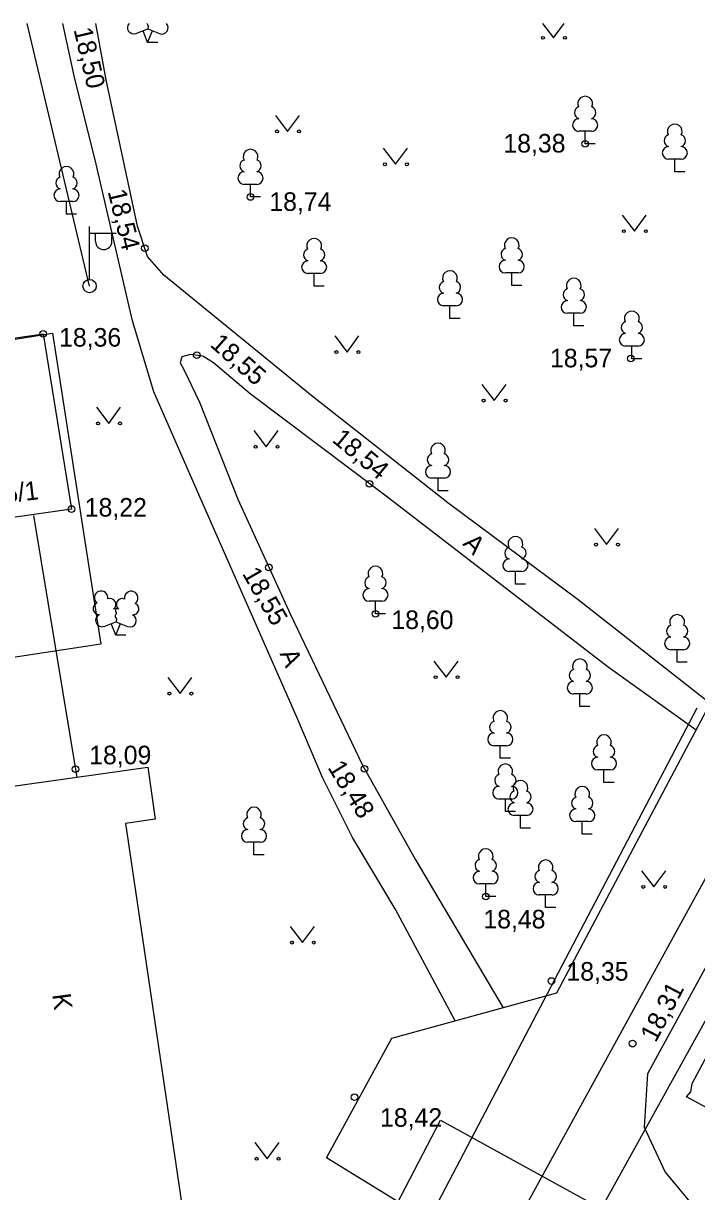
# Model space of a CAD drawing. Extents: x 713540 to 713867, y 6589774 to 6590061.
# Drawn here: x 713723 to 713748.39, y 6590016.58 to 6590060.64 of the extents above; entities that cross this region are included whole.
import ezdxf

# ---------------------------------------------------------------- set-up
doc = ezdxf.new("R2010")
doc.units = 0
for name, color, linetype in [('HALJASTUS', 7, 'Continuous'), ('HOONE', 7, 'Continuous'), ('HOONEDET', 7, 'Continuous'), ('KORGUS', 7, 'Continuous'), ('MPKAABEL', 7, 'Continuous'), ('POST', 7, 'Continuous'), ('PUU', 7, 'Continuous'), ('TEE', 7, 'Continuous'), ('TTRASS', 7, 'Continuous'), ('Слой 1', 7, 'Continuous')]:
    doc.layers.add(name, color=color, linetype=linetype)

msp = doc.modelspace()

# ---------------------------------------------------------------- linework, layer by layer
at = {"layer": 'HALJASTUS'}
for p, q in [((713742.583, 6590060.636), (713743, 6590060.09)), ((713743, 6590060.09), (713743.401, 6590060.636)), ((713732.507, 6590057.167), (713732.97, 6590056.56)), ((713732.97, 6590056.56), (713733.416, 6590057.167)), ((713736.577, 6590055.927), (713737.04, 6590055.32)), ((713737.04, 6590055.32), (713737.486, 6590055.927)), ((713745.587, 6590053.407), (713746.05, 6590052.8)), ((713746.05, 6590052.8), (713746.496, 6590053.407)), ((713734.747, 6590048.847), (713735.21, 6590048.24)), ((713735.21, 6590048.24), (713735.656, 6590048.847)), ((713740.297, 6590047.017), (713740.76, 6590046.41)), ((713740.76, 6590046.41), (713741.206, 6590047.017)), ((713725.757, 6590046.157), (713726.22, 6590045.55)), ((713726.22, 6590045.55), (713726.666, 6590046.157)), ((713731.697, 6590045.277), (713732.16, 6590044.67)), ((713732.16, 6590044.67), (713732.606, 6590045.277)), ((713744.537, 6590041.587), (713745, 6590040.98)), ((713745, 6590040.98), (713745.446, 6590041.587)), ((713738.487, 6590036.587), (713738.95, 6590035.98)), ((713738.95, 6590035.98), (713739.396, 6590036.587)), ((713728.447, 6590035.967), (713728.91, 6590035.36)), ((713728.91, 6590035.36), (713729.356, 6590035.967)), ((713746.317, 6590028.677), (713746.78, 6590028.07)), ((713746.78, 6590028.07), (713747.226, 6590028.677)), ((713733.067, 6590026.577), (713733.53, 6590025.97)), ((713733.53, 6590025.97), (713733.976, 6590026.577)), ((713731.737, 6590018.427), (713732.2, 6590017.82)), ((713732.2, 6590017.82), (713732.646, 6590018.427))]:
    msp.add_line(p, q, dxfattribs=at)
for centre in [(713742.599, 6590060.09), (713743.428, 6590060.09), (713732.569, 6590056.56), (713733.398, 6590056.56), (713736.639, 6590055.32), (713737.468, 6590055.32), (713745.649, 6590052.8), (713746.478, 6590052.8), (713734.809, 6590048.24), (713735.638, 6590048.24), (713740.359, 6590046.41), (713741.188, 6590046.41), (713725.819, 6590045.55), (713726.648, 6590045.55), (713731.759, 6590044.67), (713732.588, 6590044.67), (713744.599, 6590040.98), (713745.428, 6590040.98), (713738.549, 6590035.98), (713739.378, 6590035.98), (713728.509, 6590035.36), (713729.338, 6590035.36), (713746.379, 6590028.07), (713747.208, 6590028.07), (713733.129, 6590025.97), (713733.958, 6590025.97), (713731.799, 6590017.82), (713732.628, 6590017.82)]:
    msp.add_circle(centre, 0.055, dxfattribs=at)
at = {"layer": 'HOONE'}
for points in [[(713711.51, 6590047.14), (713723.75, 6590048.93), (713724.82, 6590042.32), (713712.76, 6590040.59), (713711.51, 6590047.14)], [(713729.99, 6589999.65), (713748.41, 6590034.82)], [(713720.1, 6590031.52), (713727.7, 6590032.58), (713727.97, 6590030.62), (713726.86, 6590030.46), (713729.03, 6590015.74), (713722.42, 6590014.82), (713720.1, 6590031.52)]]:
    msp.add_lwpolyline(points, dxfattribs=at)
at = {"layer": 'HOONEDET'}
msp.add_lwpolyline([(713764.214, 6590011.385), (713748.01, 6590020.15), (713748.17, 6590020.34), (713748.23, 6590020.65), (713753, 6590029.57)], dxfattribs=at)
at = {"layer": 'KORGUS'}
for centre in [(713744.19, 6590056.09), (713731.57, 6590054.09), (713727.58, 6590052.16), (713723.75, 6590048.93), (713729.54, 6590048.12), (713745.91, 6590048), (713736.06, 6590043.27), (713724.82, 6590042.32), (713732.26, 6590040.12), (713736.28, 6590038.37), (713724.97, 6590032.51), (713735.87, 6590032.52), (713740.44, 6590027.71), (713742.92, 6590024.52), (713745.98, 6590022.16), (713735.49, 6590020.14)]:
    msp.add_circle(centre, 0.125, dxfattribs=at)
at = {"layer": 'MPKAABEL'}
for points in [[(713725.5, 6590050.73), (713723.14, 6590060.636)], [(713734.86, 6589982.939), (713729.11, 6589985.97), (713735.68, 6589998.99), (713741.04, 6590009.14), (713752.51, 6590029.86)]]:
    msp.add_lwpolyline(points, dxfattribs=at)
at = {"layer": 'POST'}
for p, q in [((713725.5, 6590050.98), (713725.5, 6590052.98)), ((713725.5, 6590052.73), (713726.5, 6590052.73)), ((713725.727, 6590052.409), (713725.727, 6590052.73)), ((713726.339, 6590052.409), (713726.339, 6590052.73))]:
    msp.add_line(p, q, dxfattribs=at)
msp.add_circle((713725.5, 6590050.73), 0.25, dxfattribs=at)
msp.add_arc((713726.033, 6590052.409), 0.306, 180, 0, dxfattribs=at)
at = {"layer": 'PUU'}
for p, q in [((713727.25, 6590060.255), (713727.695, 6590060.43)), ((713727.69, 6590059.92), (713727.515, 6590060.36)), ((713727.69, 6590059.92), (713727.87, 6590060.36)), ((713727.695, 6590060.43), (713728.135, 6590060.25)), ((713728.07, 6590059.92), (713727.69, 6590059.92)), ((713744.43, 6590056.565), (713743.95, 6590056.565)), ((713744.19, 6590056.09), (713744.19, 6590056.565)), ((713744.57, 6590056.09), (713744.19, 6590056.09)), ((713747.81, 6590055.515), (713747.33, 6590055.515)), ((713747.57, 6590055.04), (713747.57, 6590055.515)), ((713747.95, 6590055.04), (713747.57, 6590055.04)), ((713731.81, 6590054.565), (713731.33, 6590054.565)), ((713731.57, 6590054.09), (713731.57, 6590054.565)), ((713724.87, 6590053.915), (713724.39, 6590053.915)), ((713724.63, 6590053.44), (713724.63, 6590053.915)), ((713731.95, 6590054.09), (713731.57, 6590054.09)), ((713725.01, 6590053.44), (713724.63, 6590053.44)), ((713734.21, 6590051.205), (713733.73, 6590051.205)), ((713733.97, 6590050.73), (713733.97, 6590051.205)), ((713741.66, 6590051.225), (713741.18, 6590051.225)), ((713741.42, 6590050.75), (713741.42, 6590051.225)), ((713734.35, 6590050.73), (713733.97, 6590050.73)), ((713741.8, 6590050.75), (713741.42, 6590050.75)), ((713739.33, 6590049.985), (713738.85, 6590049.985)), ((713739.09, 6590049.51), (713739.09, 6590049.985)), ((713739.47, 6590049.51), (713739.09, 6590049.51)), ((713744, 6590049.705), (713743.52, 6590049.705)), ((713743.76, 6590049.23), (713743.76, 6590049.705)), ((713744.14, 6590049.23), (713743.76, 6590049.23)), ((713746.19, 6590048.465), (713745.71, 6590048.465)), ((713745.95, 6590047.99), (713745.95, 6590048.465)), ((713746.33, 6590047.99), (713745.95, 6590047.99)), ((713738.88, 6590043.485), (713738.4, 6590043.485)), ((713738.64, 6590043.01), (713738.64, 6590043.485)), ((713739.02, 6590043.01), (713738.64, 6590043.01)), ((713741.8, 6590039.965), (713741.32, 6590039.965)), ((713741.56, 6590039.49), (713741.56, 6590039.965)), ((713741.94, 6590039.49), (713741.56, 6590039.49)), ((713736.52, 6590038.845), (713736.04, 6590038.845)), ((713736.28, 6590038.37), (713736.28, 6590038.845)), ((713726.05, 6590037.895), (713726.495, 6590038.07)), ((713726.495, 6590038.07), (713726.935, 6590037.89)), ((713736.66, 6590038.37), (713736.28, 6590038.37)), ((713726.49, 6590037.56), (713726.315, 6590038)), ((713726.49, 6590037.56), (713726.67, 6590038)), ((713726.87, 6590037.56), (713726.49, 6590037.56)), ((713747.9, 6590037.015), (713747.42, 6590037.015)), ((713747.66, 6590036.54), (713747.66, 6590037.015)), ((713748.04, 6590036.54), (713747.66, 6590036.54)), ((713744.23, 6590035.345), (713743.75, 6590035.345)), ((713743.99, 6590034.87), (713743.99, 6590035.345)), ((713744.37, 6590034.87), (713743.99, 6590034.87)), ((713741.23, 6590033.395), (713740.75, 6590033.395)), ((713740.99, 6590032.92), (713740.99, 6590033.395)), ((713741.37, 6590032.92), (713740.99, 6590032.92)), ((713745.14, 6590032.485), (713744.66, 6590032.485)), ((713744.9, 6590032.01), (713744.9, 6590032.485)), ((713745.28, 6590032.01), (713744.9, 6590032.01)), ((713741.42, 6590031.385), (713740.94, 6590031.385)), ((713741.18, 6590030.91), (713741.18, 6590031.385)), ((713741.56, 6590030.91), (713741.18, 6590030.91)), ((713741.99, 6590030.765), (713741.51, 6590030.765)), ((713741.75, 6590030.29), (713741.75, 6590030.765)), ((713744.32, 6590030.535), (713743.84, 6590030.535)), ((713744.08, 6590030.06), (713744.08, 6590030.535)), ((713742.13, 6590030.29), (713741.75, 6590030.29)), ((713731.94, 6590029.755), (713731.46, 6590029.755)), ((713731.7, 6590029.28), (713731.7, 6590029.755)), ((713744.46, 6590030.06), (713744.08, 6590030.06)), ((713732.08, 6590029.28), (713731.7, 6590029.28)), ((713740.68, 6590028.185), (713740.2, 6590028.185)), ((713740.44, 6590027.71), (713740.44, 6590028.185)), ((713740.82, 6590027.71), (713740.44, 6590027.71)), ((713742.94, 6590027.765), (713742.46, 6590027.765)), ((713742.7, 6590027.29), (713742.7, 6590027.765)), ((713743.08, 6590027.29), (713742.7, 6590027.29))]:
    msp.add_line(p, q, dxfattribs=at)
for points in [[(713727.665, 6590060.635), (713727.67, 6590060.62), (713727.68, 6590060.59), (713727.715, 6590060.53), (713727.72, 6590060.51), (713727.715, 6590060.49), (713727.7, 6590060.455), (713727.695, 6590060.43)], [(713726.495, 6590038.565), (713726.475, 6590038.49), (713726.475, 6590038.47), (713726.485, 6590038.44), (713726.505, 6590038.405), (713726.51, 6590038.385), (713726.495, 6590038.35), (713726.47, 6590038.3), (713726.465, 6590038.275), (713726.47, 6590038.26), (713726.48, 6590038.23), (713726.515, 6590038.17), (713726.52, 6590038.15), (713726.515, 6590038.13), (713726.5, 6590038.095), (713726.495, 6590038.07)]]:
    msp.add_lwpolyline(points, dxfattribs=at)
for centre, radius, start, end in [((713727.164, 6590060.478), 0.237, 138.4007, 291.5004), ((713728.225, 6590060.47), 0.237, 247.6166, 44.2946), ((713744.19, 6590057.61), 0.277, 332.5799, 207.4201), ((713744.02, 6590057.263), 0.233, 109.0217, 253.1415), ((713744.36, 6590057.263), 0.233, 286.8508, 70.9859), ((713743.953, 6590056.802), 0.238, 90.0016, 269.3953), ((713744.427, 6590056.802), 0.238, 270.6047, 89.9984), ((713747.57, 6590056.56), 0.277, 332.5799, 207.4201), ((713747.4, 6590056.213), 0.233, 109.0217, 253.1415), ((713747.74, 6590056.213), 0.233, 286.8508, 70.9859), ((713731.57, 6590055.61), 0.277, 332.5799, 207.4201), ((713747.333, 6590055.752), 0.238, 90.0016, 269.3953), ((713747.807, 6590055.752), 0.238, 270.6047, 89.9984), ((713724.63, 6590054.96), 0.277, 332.5799, 207.4201), ((713731.4, 6590055.263), 0.233, 109.0217, 253.1415), ((713731.74, 6590055.263), 0.233, 286.8508, 70.9859), ((713724.46, 6590054.613), 0.233, 109.0217, 253.1415), ((713724.8, 6590054.613), 0.233, 286.8508, 70.9859), ((713731.333, 6590054.802), 0.238, 90.0016, 269.3953), ((713731.807, 6590054.802), 0.238, 270.6047, 89.9984), ((713724.393, 6590054.152), 0.238, 90.0016, 269.3953), ((713724.867, 6590054.152), 0.238, 270.6047, 89.9984), ((713733.8, 6590051.903), 0.233, 109.0217, 253.1415), ((713733.97, 6590052.25), 0.277, 332.5799, 207.4201), ((713734.14, 6590051.903), 0.233, 286.8508, 70.9859), ((713741.25, 6590051.923), 0.233, 109.0217, 253.1415), ((713741.42, 6590052.27), 0.277, 332.5799, 207.4201), ((713741.59, 6590051.923), 0.233, 286.8508, 70.9859), ((713733.733, 6590051.442), 0.238, 90.0016, 269.3953), ((713734.207, 6590051.442), 0.238, 270.6047, 89.9984), ((713741.183, 6590051.462), 0.238, 90.0016, 269.3953), ((713741.657, 6590051.462), 0.238, 270.6047, 89.9984), ((713739.09, 6590051.03), 0.277, 332.5799, 207.4201), ((713738.92, 6590050.683), 0.233, 109.0217, 253.1415), ((713739.26, 6590050.683), 0.233, 286.8508, 70.9859), ((713743.76, 6590050.75), 0.277, 332.5799, 207.4201), ((713738.853, 6590050.222), 0.238, 90.0016, 269.3953), ((713739.327, 6590050.222), 0.238, 270.6047, 89.9984), ((713743.59, 6590050.403), 0.233, 109.0217, 253.1415), ((713743.93, 6590050.403), 0.233, 286.8508, 70.9859), ((713743.523, 6590049.942), 0.238, 90.0016, 269.3953), ((713743.997, 6590049.942), 0.238, 270.6047, 89.9984), ((713745.95, 6590049.51), 0.277, 332.5799, 207.4201), ((713745.78, 6590049.163), 0.233, 109.0217, 253.1415), ((713746.12, 6590049.163), 0.233, 286.8508, 70.9859), ((713745.713, 6590048.702), 0.238, 90.0016, 269.3953), ((713746.187, 6590048.702), 0.238, 270.6047, 89.9984), ((713738.64, 6590044.53), 0.277, 332.5799, 207.4201), ((713738.47, 6590044.183), 0.233, 109.0217, 253.1415), ((713738.81, 6590044.183), 0.233, 286.8508, 70.9859), ((713738.403, 6590043.722), 0.238, 90.0016, 269.3953), ((713738.877, 6590043.722), 0.238, 270.6047, 89.9984), ((713741.56, 6590041.01), 0.277, 332.5799, 207.4201), ((713741.39, 6590040.663), 0.233, 109.0217, 253.1415), ((713741.73, 6590040.663), 0.233, 286.8508, 70.9859), ((713741.323, 6590040.202), 0.238, 90.0016, 269.3953), ((713741.797, 6590040.202), 0.238, 270.6047, 89.9984), ((713736.28, 6590039.89), 0.277, 332.5799, 207.4201), ((713736.11, 6590039.543), 0.233, 109.0217, 253.1415), ((713736.45, 6590039.543), 0.233, 286.8508, 70.9859), ((713725.933, 6590038.974), 0.256, 111.5027, 232.5173), ((713725.933, 6590038.974), 0.256, 350.4856, 111.5002), ((713726.268, 6590038.724), 0.224, 308.5041, 111.5725), ((713726.731, 6590038.719), 0.225, 67.7016, 230.5126), ((713727.069, 6590038.965), 0.256, 67.6168, 188.6314), ((713727.069, 6590038.965), 0.256, 306.5997, 67.6143), ((713736.043, 6590039.082), 0.238, 90.0016, 269.3953), ((713736.517, 6590039.082), 0.238, 270.6047, 89.9984), ((713725.859, 6590038.563), 0.224, 111.4304, 274.4987), ((713726.494, 6590038.327), 0.237, 66.7655, 111.5015), ((713727.136, 6590038.553), 0.224, 264.6183, 67.6866), ((713725.964, 6590038.118), 0.237, 111.5014, 291.5004), ((713727.025, 6590038.11), 0.237, 247.6166, 67.6155), ((713747.66, 6590038.06), 0.277, 332.5799, 207.4201), ((713747.49, 6590037.713), 0.233, 109.0217, 253.1415), ((713747.83, 6590037.713), 0.233, 286.8508, 70.9859), ((713747.423, 6590037.252), 0.238, 90.0016, 269.3953), ((713747.897, 6590037.252), 0.238, 270.6047, 89.9984), ((713743.82, 6590036.043), 0.233, 109.0217, 253.1415), ((713743.99, 6590036.39), 0.277, 332.5799, 207.4201), ((713744.16, 6590036.043), 0.233, 286.8508, 70.9859), ((713743.753, 6590035.582), 0.238, 90.0016, 269.3953), ((713744.227, 6590035.582), 0.238, 270.6047, 89.9984), ((713740.99, 6590034.44), 0.277, 332.5799, 207.4201), ((713740.82, 6590034.093), 0.233, 109.0217, 253.1415), ((713741.16, 6590034.093), 0.233, 286.8508, 70.9859), ((713740.753, 6590033.632), 0.238, 90.0016, 269.3953), ((713741.227, 6590033.632), 0.238, 270.6047, 89.9984), ((713744.9, 6590033.53), 0.277, 332.5799, 207.4201), ((713744.73, 6590033.183), 0.233, 109.0217, 253.1415), ((713745.07, 6590033.183), 0.233, 286.8508, 70.9859), ((713744.663, 6590032.722), 0.238, 90.0016, 269.3953), ((713745.137, 6590032.722), 0.238, 270.6047, 89.9984), ((713741.01, 6590032.083), 0.233, 109.0217, 253.1415), ((713741.18, 6590032.43), 0.277, 332.5799, 207.4201), ((713741.35, 6590032.083), 0.233, 286.8508, 70.9859), ((713740.943, 6590031.622), 0.238, 90.0016, 269.3953), ((713741.417, 6590031.622), 0.238, 270.6047, 89.9984), ((713741.75, 6590031.81), 0.277, 332.5799, 207.4201), ((713744.08, 6590031.58), 0.277, 332.5799, 207.4201), ((713741.58, 6590031.463), 0.233, 109.0217, 253.1415), ((713741.92, 6590031.463), 0.233, 286.8508, 70.9859), ((713743.91, 6590031.233), 0.233, 109.0217, 253.1415), ((713744.25, 6590031.233), 0.233, 286.8508, 70.9859), ((713731.7, 6590030.8), 0.277, 332.5799, 207.4201), ((713741.513, 6590031.002), 0.238, 90.0016, 269.3953), ((713741.987, 6590031.002), 0.238, 270.6047, 89.9984), ((713743.843, 6590030.772), 0.238, 90.0016, 269.3953), ((713744.317, 6590030.772), 0.238, 270.6047, 89.9984), ((713731.53, 6590030.453), 0.233, 109.0217, 253.1415), ((713731.87, 6590030.453), 0.233, 286.8508, 70.9859), ((713731.463, 6590029.992), 0.238, 90.0016, 269.3953), ((713731.937, 6590029.992), 0.238, 270.6047, 89.9984), ((713740.44, 6590029.23), 0.277, 332.5799, 207.4201), ((713740.27, 6590028.883), 0.233, 109.0217, 253.1415), ((713740.61, 6590028.883), 0.233, 286.8508, 70.9859), ((713742.7, 6590028.81), 0.277, 332.5799, 207.4201), ((713740.203, 6590028.422), 0.238, 90.0016, 269.3953), ((713740.677, 6590028.422), 0.238, 270.6047, 89.9984), ((713742.53, 6590028.463), 0.233, 109.0217, 253.1415), ((713742.87, 6590028.463), 0.233, 286.8508, 70.9859), ((713742.463, 6590028.002), 0.238, 90.0016, 269.3953), ((713742.937, 6590028.002), 0.238, 270.6047, 89.9984)]:
    msp.add_arc(centre, radius, start, end, dxfattribs=at)
at = {"layer": 'TEE'}
for points in [[(713739.289, 6590023.021), (713737.03, 6590027.24), (713735.42, 6590029.93), (713734.29, 6590032.19), (713733.31, 6590034.47), (713729.71, 6590042.67), (713727.92, 6590046.74), (713727.12, 6590049.42), (713725.75, 6590055.32), (713724.92, 6590058.66), (713724.485, 6590060.636)], [(713748.91, 6590034.986), (713743.93, 6590038.9), (713739.01, 6590042.56), (713733.9, 6590046.58), (713728.3, 6590051.14), (713727.69, 6590051.85), (713727.31, 6590052.99), (713726.13, 6590058.51), (713725.741, 6590060.636)], [(713748.377, 6590033.981), (713745.06, 6590036.36), (713736.69, 6590042.8), (713731.56, 6590046.66), (713730.17, 6590047.84), (713729.77, 6590048.09), (713729.31, 6590048.15), (713728.98, 6590048.06), (713728.91, 6590047.84), (713729.05, 6590047.58), (713729.64, 6590046.35), (713731.09, 6590042.69), (713733.06, 6590038.37), (713735.79, 6590032.66), (713737.78, 6590029.12), (713741.093, 6590023.514)], [(713750.927, 6590008.03), (713744.522, 6590011.657), (713734.435, 6590017.847), (713736.903, 6590022.368), (713743.125, 6590024.07), (713753.784, 6590044.184), (713757.249, 6590042.712), (713751.718, 6590032.993), (713753.469, 6590031.801), (713752.46, 6590029.762), (713751.314, 6590029.769), (713746.538, 6590021.024), (713746.409, 6590019.015), (713747.208, 6590017.314), (713749.179, 6590014.931), (713751.617, 6590012.967), (713761.092, 6590007.257)], [(713723.39, 6590042.08), (713725.02, 6590032.2)]]:
    msp.add_lwpolyline(points, dxfattribs=at)
at = {"layer": 'TTRASS'}
msp.add_lwpolyline([(713750, 6590030.71), (713740.74, 6590013.84), (713731.96, 6589996.83)], dxfattribs=at)
at = {"layer": 'Слой 1'}
for points in [[(713713.69, 6590035.37), (713713.11, 6590039.08), (713711.87, 6590047), (713716.35, 6590047.71), (713724.1, 6590048.95), (713725.92, 6590037.22)], [(713738.74, 6590019.27), (713761.62, 6590006.68), (713742.5, 6589970.55), (713719.65, 6589982.59)]]:
    msp.add_lwpolyline(points, close=True, dxfattribs=at)

# ---------------------------------------------------------------- texts
at = {"layer": 'HOONE'}
for s, rotation, p in [('5/1', 6.7351, (713722.315, 6590042.539)), ('K', 277.4459, (713724.089, 6590024.012))]:
    msp.add_text(s, height=0.7, rotation=rotation, dxfattribs=at).set_placement(p)
at = {"layer": 'KORGUS'}
for s, rotation, p in [('18,50', 283.1229, (713724.893, 6590060.403)), ('18,54', 283.8303, (713726.178, 6590054.295)), ('18,55', 318.6982, (713730.007, 6590048.479)), ('18,54', 320.3787, (713734.612, 6590044.878)), ('18,55', 300.0032, (713731.238, 6590039.884)), ('18,48', 301.8065, (713734.459, 6590032.574)), ('18,31', 62.2597, (713746.851, 6590022.171))]:
    msp.add_text(s, height=0.7, rotation=rotation, dxfattribs=at).set_placement(p)
for s, p in [('18,38', (713741.106, 6590055.765)), ('18,74', (713732.278, 6590053.565)), ('18,36', (713724.35, 6590048.445)), ('18,57', (713742.863, 6590047.665)), ('18,22', (713725.318, 6590042.035)), ('18,60', (713736.881, 6590037.795)), ('18,09', (713725.486, 6590032.695)), ('18,48', (713740.351, 6590026.505)), ('18,35', (713743.483, 6590024.535)), ('18,42', (713736.453, 6590019.025))]:
    msp.add_text(s, height=0.7, dxfattribs=at).set_placement(p)
at = {"layer": 'TEE'}
for rotation, p in [(314.6124, (713739.543, 6590040.988)), (293.3986, (713732.657, 6590036.868))]:
    msp.add_text('A', height=0.7, rotation=rotation, dxfattribs=at).set_placement(p)

doc.saveas('drawing.dxf')
